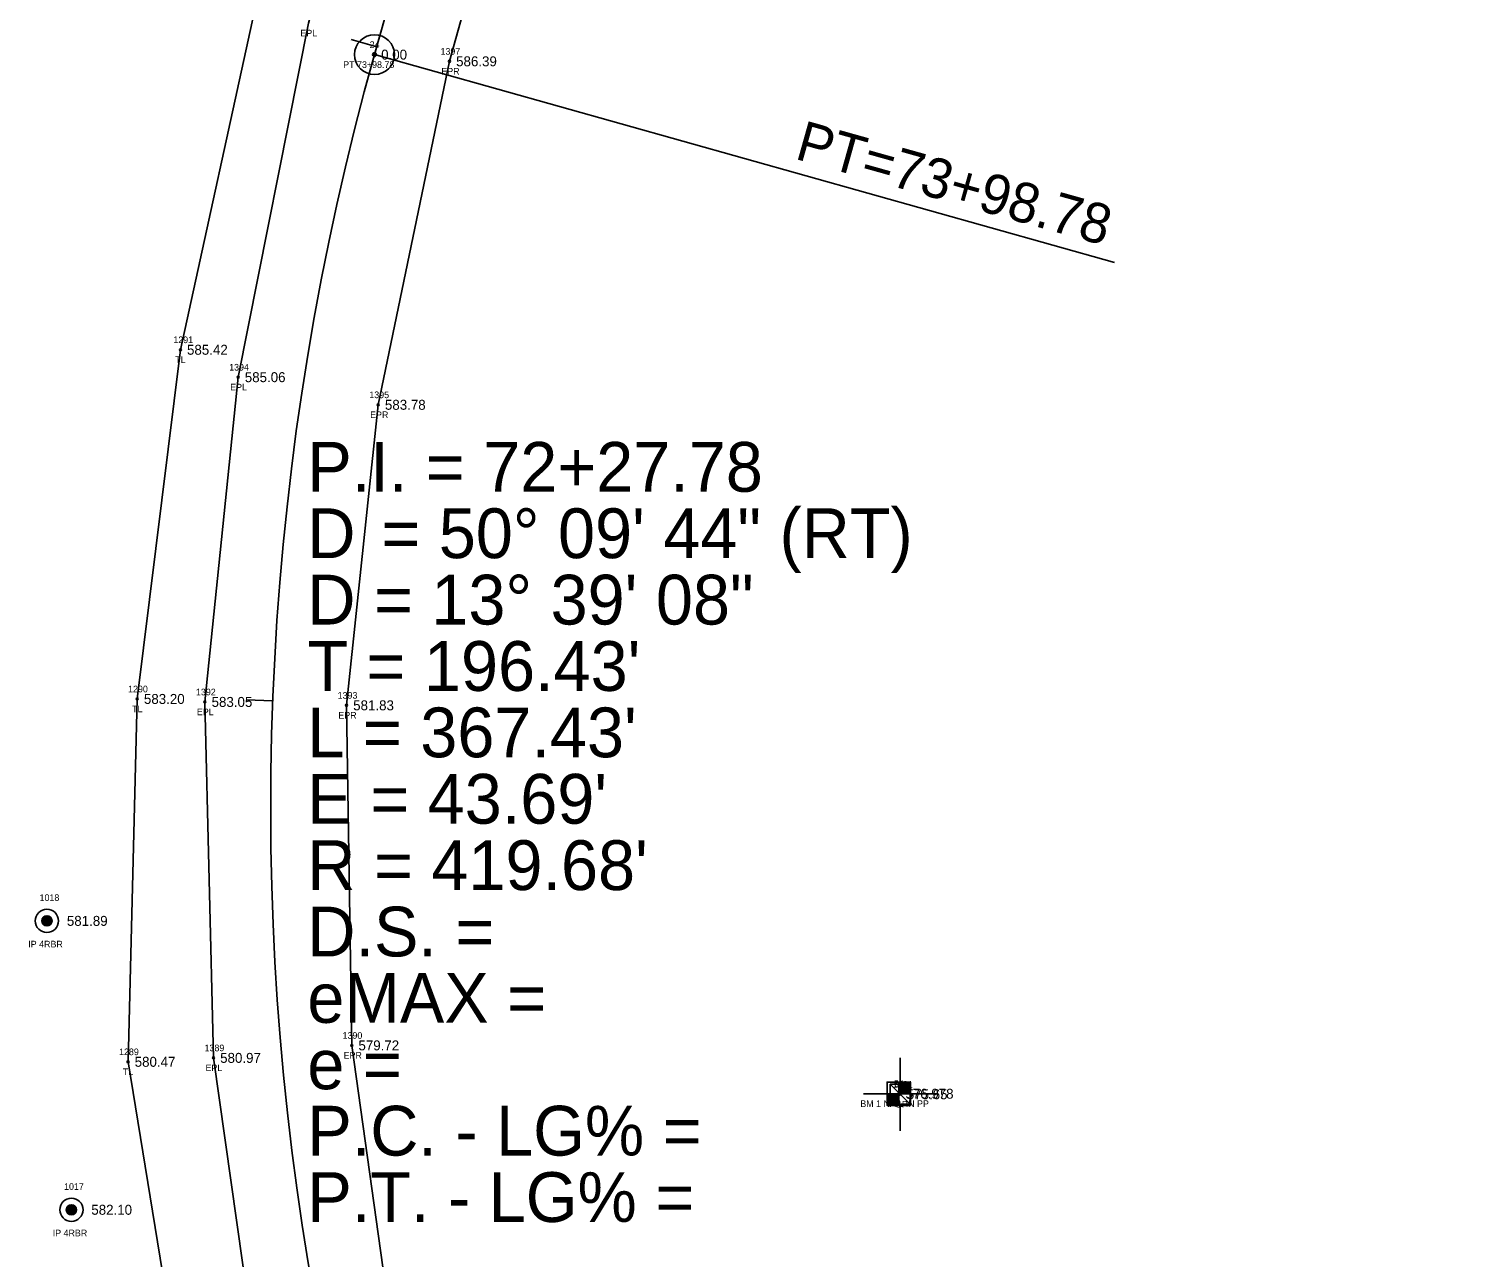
# Model space of a CAD drawing. Extents: x 1694813 to 1696862, y 1086485 to 1091027.
# Drawn here: x 1695680.1 to 1695899, y 1089351.6 to 1089536.7 of the extents above; entities that cross this region are included whole.
import ezdxf

# ---------------------------------------------------------------- set-up
doc = ezdxf.new("R2010")
doc.units = 0
for name, color, linetype in [('RD_EX_DV_Prop_txCode', 7, 'Continuous'), ('RD_EX_DV_PropPin', 7, 'Continuous'), ('RD_EX_Road', 7, 'Continuous'), ('RD_EX_Road_txCode', 7, 'Continuous'), ('RD_EX_TX_DV_Prop_ELEV', 7, 'Continuous'), ('RD_EX_TX_Road_ELEV', 7, 'Continuous'), ('RD_EX_TX_UT_ELEV', 7, 'Continuous'), ('RD_EX_TX_VEG_ELEV', 7, 'Continuous'), ('RD_EX_UT', 7, 'Continuous'), ('RD_EX_UT_txCode', 7, 'Continuous'), ('RD_EX_VEG', 7, 'Continuous'), ('RD_EX_VEG_txCode', 7, 'Continuous'), ('RD_HC_Cl', 7, 'Continuous'), ('RD_HC_Data', 7, 'Continuous'), ('RD_HC_Data_Tic', 7, 'Continuous'), ('RD_HC_Survey', 7, 'Continuous'), ('RD_HC_Survey_ELEV', 7, 'Continuous'), ('RD_HC_Survey_txCode', 7, 'Continuous'), ('RD_HC_txCode', 7, 'Continuous'), ('RD_SMD_Locator', 7, 'Continuous')]:
    doc.layers.add(name, color=color, linetype=linetype)

msp = doc.modelspace()

# ---------------------------------------------------------------- linework, layer by layer
at = {"layer": 'RD_EX_DV_PropPin'}
for p, q in [((1695682.05, 1089402.17), (1695682.05, 1089402.56)), ((1695682.09, 1089402.07), (1695682.09, 1089402.66)), ((1695682.12, 1089401.99), (1695682.12, 1089402.73)), ((1695682.16, 1089401.94), (1695682.16, 1089402.79)), ((1695682.19, 1089401.89), (1695682.19, 1089402.84)), ((1695682.23, 1089401.85), (1695682.23, 1089402.88)), ((1695682.26, 1089401.81), (1695682.26, 1089402.91)), ((1695682.3, 1089401.78), (1695682.3, 1089402.95)), ((1695682.33, 1089401.75), (1695682.33, 1089402.97)), ((1695682.37, 1089401.73), (1695682.37, 1089403)), ((1695682.4, 1089401.71), (1695682.4, 1089403.02)), ((1695682.44, 1089401.69), (1695682.44, 1089403.04)), ((1695682.47, 1089401.67), (1695682.47, 1089403.06)), ((1695682.51, 1089401.66), (1695682.51, 1089403.07)), ((1695682.54, 1089401.64), (1695682.54, 1089403.08)), ((1695682.58, 1089401.63), (1695682.58, 1089403.1)), ((1695682.61, 1089401.62), (1695682.61, 1089403.1)), ((1695682.65, 1089401.62), (1695682.65, 1089403.11)), ((1695682.68, 1089401.61), (1695682.68, 1089403.12)), ((1695682.72, 1089401.61), (1695682.72, 1089403.12)), ((1695682.75, 1089401.6), (1695682.75, 1089403.12)), ((1695682.79, 1089401.6), (1695682.79, 1089403.12)), ((1695682.82, 1089401.6), (1695682.82, 1089403.12)), ((1695682.86, 1089401.61), (1695682.86, 1089403.12)), ((1695682.89, 1089401.61), (1695682.89, 1089403.12)), ((1695682.93, 1089401.62), (1695682.93, 1089403.11)), ((1695682.96, 1089401.62), (1695682.96, 1089403.1)), ((1695683, 1089401.63), (1695683, 1089403.1)), ((1695683.03, 1089401.64), (1695683.03, 1089403.08)), ((1695683.07, 1089401.66), (1695683.07, 1089403.07)), ((1695683.1, 1089401.67), (1695683.1, 1089403.06)), ((1695683.14, 1089401.69), (1695683.14, 1089403.04)), ((1695683.17, 1089401.71), (1695683.17, 1089403.02)), ((1695683.21, 1089401.73), (1695683.21, 1089403)), ((1695683.24, 1089401.75), (1695683.24, 1089402.97)), ((1695683.28, 1089401.78), (1695683.28, 1089402.95)), ((1695683.31, 1089401.81), (1695683.31, 1089402.91)), ((1695683.35, 1089401.85), (1695683.35, 1089402.88)), ((1695683.38, 1089401.89), (1695683.38, 1089402.84)), ((1695683.42, 1089401.94), (1695683.42, 1089402.79)), ((1695683.45, 1089401.99), (1695683.45, 1089402.73)), ((1695683.49, 1089402.07), (1695683.49, 1089402.66)), ((1695683.52, 1089402.17), (1695683.52, 1089402.56)), ((1695685.73, 1089358.64), (1695685.73, 1089359.03)), ((1695685.77, 1089358.54), (1695685.77, 1089359.14)), ((1695685.8, 1089358.47), (1695685.8, 1089359.21)), ((1695685.84, 1089358.41), (1695685.84, 1089359.26)), ((1695685.87, 1089358.36), (1695685.87, 1089359.31)), ((1695685.91, 1089358.32), (1695685.91, 1089359.35)), ((1695685.94, 1089358.29), (1695685.94, 1089359.39)), ((1695685.98, 1089358.26), (1695685.98, 1089359.42)), ((1695686.01, 1089358.23), (1695686.01, 1089359.45)), ((1695686.05, 1089358.2), (1695686.05, 1089359.47)), ((1695686.08, 1089358.18), (1695686.08, 1089359.49)), ((1695686.12, 1089358.16), (1695686.12, 1089359.51)), ((1695686.15, 1089358.15), (1695686.15, 1089359.53)), ((1695686.19, 1089358.13), (1695686.19, 1089359.55)), ((1695686.22, 1089358.12), (1695686.22, 1089359.56)), ((1695686.26, 1089358.11), (1695686.26, 1089359.57)), ((1695686.29, 1089358.1), (1695686.29, 1089359.58)), ((1695686.33, 1089358.09), (1695686.33, 1089359.59)), ((1695686.36, 1089358.08), (1695686.36, 1089359.59)), ((1695686.4, 1089358.08), (1695686.4, 1089359.6)), ((1695686.43, 1089358.08), (1695686.43, 1089359.6)), ((1695686.47, 1089358.08), (1695686.47, 1089359.6)), ((1695686.5, 1089358.08), (1695686.5, 1089359.6)), ((1695686.54, 1089358.08), (1695686.54, 1089359.6)), ((1695686.57, 1089358.08), (1695686.57, 1089359.59)), ((1695686.61, 1089358.09), (1695686.61, 1089359.59)), ((1695686.64, 1089358.1), (1695686.64, 1089359.58)), ((1695686.68, 1089358.11), (1695686.68, 1089359.57)), ((1695686.71, 1089358.12), (1695686.71, 1089359.56)), ((1695686.75, 1089358.13), (1695686.75, 1089359.55)), ((1695686.78, 1089358.15), (1695686.78, 1089359.53)), ((1695686.82, 1089358.16), (1695686.82, 1089359.51)), ((1695686.85, 1089358.18), (1695686.85, 1089359.49)), ((1695686.89, 1089358.2), (1695686.89, 1089359.47)), ((1695686.92, 1089358.23), (1695686.92, 1089359.45)), ((1695686.96, 1089358.26), (1695686.96, 1089359.42)), ((1695686.99, 1089358.29), (1695686.99, 1089359.39)), ((1695687.03, 1089358.32), (1695687.03, 1089359.35)), ((1695687.06, 1089358.36), (1695687.06, 1089359.31)), ((1695687.1, 1089358.41), (1695687.1, 1089359.26)), ((1695687.13, 1089358.47), (1695687.13, 1089359.21)), ((1695687.17, 1089358.54), (1695687.17, 1089359.14)), ((1695687.2, 1089358.64), (1695687.2, 1089359.03))]:
    msp.add_line(p, q, dxfattribs=at)
for centre, radius in [((1695682.79, 1089402.36), 1.75), ((1695682.79, 1089402.36), 0.761), ((1695686.47, 1089358.84), 1.75), ((1695686.47, 1089358.84), 0.761)]:
    msp.add_circle(centre, radius, dxfattribs=at)
at = {"layer": 'RD_EX_Road'}
for points in [[(1695813.78, 1089148.1), (1695805.56, 1089142.08), (1695776.44, 1089183.94), (1695749.27, 1089231.88), (1695730.49, 1089275.72), (1695714.87, 1089332.12), (1695707.87, 1089381.72), (1695706.58, 1089435.34), (1695711.58, 1089484.26), (1695722.15, 1089537.59), (1695749.04, 1089634.88), (1695776.11, 1089730.43), (1695788.13, 1089777.42), (1695798.89, 1089826.76), (1695807.1, 1089870.03), (1695814.71, 1089923.3), (1695820.51, 1089978.16), (1695824.04, 1090019.79), (1695832.76, 1090119.06), (1695841.25, 1090216.76), (1695850.36, 1090314.41), (1695859.24, 1090411.82), (1695868.09, 1090511.63), (1695876.75, 1090608.38)], [(1695735.35, 1089335.84), (1695728.69, 1089383.6), (1695727.9, 1089434.83), (1695732.68, 1089480.1), (1695743.4, 1089531.84), (1695770.35, 1089628.36), (1695797.63, 1089725.22), (1695809.49, 1089772.37), (1695818.34, 1089811.57), (1695820.65, 1089823.41), (1695822.99, 1089835.26), (1695829.18, 1089869.37), (1695836.32, 1089920.97), (1695842.44, 1089975.46), (1695846.49, 1090018.55), (1695849.32, 1090055.39), (1695850.91, 1090072.92), (1695855.09, 1090117.49), (1695863.53, 1090214.93), (1695872.56, 1090312.44), (1695881.69, 1090410.78), (1695890.45, 1090509.3), (1695899.01, 1090605.4)]]:
    msp.add_lwpolyline(points, dxfattribs=at)
at = {"layer": 'RD_EX_UT'}
for p, q in [((1695811.26, 1089377.74), (1695811.26, 1089381.74)), ((1695809.73, 1089376.28), (1695805.73, 1089376.28)), ((1695812.76, 1089377.74), (1695809.76, 1089374.74)), ((1695809.76, 1089377.74), (1695812.76, 1089374.74)), ((1695812.76, 1089377.74), (1695809.76, 1089377.74)), ((1695809.76, 1089377.74), (1695809.76, 1089374.74)), ((1695812.76, 1089374.74), (1695812.76, 1089377.74)), ((1695812.77, 1089376.3), (1695816.79, 1089376.3)), ((1695809.76, 1089374.74), (1695812.76, 1089374.74)), ((1695811.26, 1089374.74), (1695811.26, 1089370.74))]:
    msp.add_line(p, q, dxfattribs=at)
at = {"layer": 'RD_EX_VEG'}
msp.add_lwpolyline([(1695703.52, 1089329.03), (1695695, 1089381.13), (1695696.39, 1089435.79), (1695702.88, 1089488.39), (1695714.38, 1089541.02), (1695736.44, 1089639.8), (1695727.2, 1089683.67), (1695743.97, 1089747.86), (1695756.74, 1089783.05), (1695766.78, 1089823.73), (1695779.53, 1089881.29), (1695754.55, 1089939.82)], dxfattribs=at)
at = {"layer": 'RD_HC_Cl'}
msp.add_line((1695732.11, 1089532.85), (1695785.9, 1089724.36), dxfattribs=at)
msp.add_arc((1696136.16, 1089419.37), 419.68, 164.3126, 214.4747, dxfattribs=at)
at = {"layer": 'RD_HC_Data'}
msp.add_line((1695732.11, 1089532.85), (1695843.51, 1089501.56), dxfattribs=at)
for radius in [3, 0.282]:
    msp.add_circle((1695732.11, 1089532.85), radius, dxfattribs=at)
at = {"layer": 'RD_HC_Data_Tic'}
for p, q in [((1695732.44, 1089534.02), (1695728.59, 1089535.11)), ((1695716.79, 1089435.5), (1695712.79, 1089435.65))]:
    msp.add_line(p, q, dxfattribs=at)
at = {"layer": 'RD_HC_Survey'}
for p, q in [((1695811.05, 1089378.07), (1695811.05, 1089374.57)), ((1695811.06, 1089378.07), (1695811.06, 1089376.32)), ((1695811.09, 1089378.07), (1695811.09, 1089376.32)), ((1695811.11, 1089378.07), (1695811.11, 1089376.32)), ((1695811.14, 1089378.07), (1695811.14, 1089376.32)), ((1695811.16, 1089378.07), (1695811.16, 1089376.32)), ((1695811.19, 1089378.07), (1695811.19, 1089376.32)), ((1695811.21, 1089378.07), (1695811.21, 1089376.32)), ((1695811.24, 1089378.07), (1695811.24, 1089376.32)), ((1695811.26, 1089378.07), (1695811.26, 1089376.32)), ((1695811.29, 1089378.07), (1695811.29, 1089376.32)), ((1695811.31, 1089378.07), (1695811.31, 1089376.32)), ((1695811.34, 1089378.07), (1695811.34, 1089376.32)), ((1695811.36, 1089378.07), (1695811.36, 1089376.32)), ((1695811.38, 1089378.07), (1695811.38, 1089376.32)), ((1695811.41, 1089378.07), (1695811.41, 1089376.32)), ((1695811.43, 1089378.07), (1695811.43, 1089376.32)), ((1695811.46, 1089378.07), (1695811.46, 1089376.32)), ((1695811.48, 1089378.07), (1695811.48, 1089376.32)), ((1695811.51, 1089378.07), (1695811.51, 1089376.32)), ((1695811.53, 1089378.07), (1695811.53, 1089376.32)), ((1695811.56, 1089378.07), (1695811.56, 1089376.32)), ((1695811.58, 1089378.07), (1695811.58, 1089376.32)), ((1695811.61, 1089378.07), (1695811.61, 1089376.32)), ((1695811.63, 1089378.07), (1695811.63, 1089376.32)), ((1695811.66, 1089378.07), (1695811.66, 1089376.32)), ((1695811.68, 1089378.07), (1695811.68, 1089376.32)), ((1695811.71, 1089378.07), (1695811.71, 1089376.32)), ((1695811.73, 1089378.07), (1695811.73, 1089376.32)), ((1695811.76, 1089378.07), (1695811.76, 1089376.32)), ((1695811.78, 1089378.07), (1695811.78, 1089376.32)), ((1695811.81, 1089378.07), (1695811.81, 1089376.32)), ((1695811.83, 1089378.07), (1695811.83, 1089376.32)), ((1695811.86, 1089378.07), (1695811.86, 1089376.32)), ((1695811.88, 1089378.07), (1695811.88, 1089376.32)), ((1695811.9, 1089378.07), (1695811.9, 1089376.32)), ((1695811.93, 1089378.07), (1695811.93, 1089376.32)), ((1695811.95, 1089378.07), (1695811.95, 1089376.32)), ((1695811.98, 1089378.07), (1695811.98, 1089376.32)), ((1695812, 1089378.07), (1695812, 1089376.32)), ((1695812.03, 1089378.07), (1695812.03, 1089376.32)), ((1695812.05, 1089378.07), (1695812.05, 1089376.32)), ((1695812.08, 1089378.07), (1695812.08, 1089376.32)), ((1695812.1, 1089378.07), (1695812.1, 1089376.32)), ((1695812.13, 1089378.07), (1695812.13, 1089376.32)), ((1695812.15, 1089378.07), (1695812.15, 1089376.32)), ((1695812.18, 1089378.07), (1695812.18, 1089376.32)), ((1695812.2, 1089378.07), (1695812.2, 1089376.32)), ((1695812.23, 1089378.07), (1695812.23, 1089376.32)), ((1695812.25, 1089378.07), (1695812.25, 1089376.32)), ((1695812.28, 1089378.07), (1695812.28, 1089376.32)), ((1695812.3, 1089378.07), (1695812.3, 1089376.32)), ((1695812.33, 1089378.07), (1695812.33, 1089376.32)), ((1695812.35, 1089378.07), (1695812.35, 1089376.32)), ((1695812.37, 1089378.07), (1695812.37, 1089376.32)), ((1695812.4, 1089378.07), (1695812.4, 1089376.32)), ((1695812.42, 1089378.07), (1695812.42, 1089376.32)), ((1695812.45, 1089378.07), (1695812.45, 1089376.32)), ((1695812.47, 1089378.07), (1695812.47, 1089376.32)), ((1695812.5, 1089378.07), (1695812.5, 1089376.32)), ((1695812.52, 1089378.07), (1695812.52, 1089376.32)), ((1695812.55, 1089378.07), (1695812.55, 1089376.32)), ((1695812.57, 1089378.07), (1695812.57, 1089376.32)), ((1695812.6, 1089378.07), (1695812.6, 1089376.32)), ((1695812.62, 1089378.07), (1695812.62, 1089376.32)), ((1695812.65, 1089378.07), (1695812.65, 1089376.32)), ((1695812.67, 1089378.07), (1695812.67, 1089376.32)), ((1695812.7, 1089378.07), (1695812.7, 1089376.32)), ((1695812.72, 1089378.07), (1695812.72, 1089376.32)), ((1695812.75, 1089378.07), (1695812.75, 1089376.32)), ((1695812.77, 1089378.07), (1695812.77, 1089376.32)), ((1695812.8, 1089376.32), (1695809.3, 1089376.32)), ((1695809.3, 1089376.32), (1695809.3, 1089374.57)), ((1695809.32, 1089376.32), (1695809.32, 1089374.57)), ((1695809.35, 1089376.32), (1695809.35, 1089374.57)), ((1695809.37, 1089376.32), (1695809.37, 1089374.57)), ((1695809.39, 1089376.32), (1695809.39, 1089374.57)), ((1695809.42, 1089376.32), (1695809.42, 1089374.57)), ((1695809.44, 1089376.32), (1695809.44, 1089374.57)), ((1695809.47, 1089376.32), (1695809.47, 1089374.57)), ((1695809.49, 1089376.32), (1695809.49, 1089374.57)), ((1695809.52, 1089376.32), (1695809.52, 1089374.57)), ((1695809.54, 1089376.32), (1695809.54, 1089374.57)), ((1695809.57, 1089376.32), (1695809.57, 1089374.57)), ((1695809.59, 1089376.32), (1695809.59, 1089374.57)), ((1695809.62, 1089376.32), (1695809.62, 1089374.57)), ((1695809.64, 1089376.32), (1695809.64, 1089374.57)), ((1695809.67, 1089376.32), (1695809.67, 1089374.57)), ((1695809.69, 1089376.32), (1695809.69, 1089374.57)), ((1695809.72, 1089376.32), (1695809.72, 1089374.57)), ((1695809.74, 1089376.32), (1695809.74, 1089374.57)), ((1695809.77, 1089376.32), (1695809.77, 1089374.57)), ((1695809.79, 1089376.32), (1695809.79, 1089374.57)), ((1695809.82, 1089376.32), (1695809.82, 1089374.57)), ((1695809.84, 1089376.32), (1695809.84, 1089374.57)), ((1695809.86, 1089376.32), (1695809.86, 1089374.57)), ((1695809.89, 1089376.32), (1695809.89, 1089374.57)), ((1695809.91, 1089376.32), (1695809.91, 1089374.57)), ((1695809.94, 1089376.32), (1695809.94, 1089374.57)), ((1695809.96, 1089376.32), (1695809.96, 1089374.57)), ((1695809.99, 1089376.32), (1695809.99, 1089374.57)), ((1695810.01, 1089376.32), (1695810.01, 1089374.57)), ((1695810.04, 1089376.32), (1695810.04, 1089374.57)), ((1695810.06, 1089376.32), (1695810.06, 1089374.57)), ((1695810.09, 1089376.32), (1695810.09, 1089374.57)), ((1695810.11, 1089376.32), (1695810.11, 1089374.57)), ((1695810.14, 1089376.32), (1695810.14, 1089374.57)), ((1695810.16, 1089376.32), (1695810.16, 1089374.57)), ((1695810.19, 1089376.32), (1695810.19, 1089374.57)), ((1695810.21, 1089376.32), (1695810.21, 1089374.57)), ((1695810.24, 1089376.32), (1695810.24, 1089374.57)), ((1695810.26, 1089376.32), (1695810.26, 1089374.57)), ((1695810.29, 1089376.32), (1695810.29, 1089374.57)), ((1695810.31, 1089376.32), (1695810.31, 1089374.57)), ((1695810.34, 1089376.32), (1695810.34, 1089374.57)), ((1695810.36, 1089376.32), (1695810.36, 1089374.57)), ((1695810.38, 1089376.32), (1695810.38, 1089374.57)), ((1695810.41, 1089376.32), (1695810.41, 1089374.57)), ((1695810.43, 1089376.32), (1695810.43, 1089374.57)), ((1695810.46, 1089376.32), (1695810.46, 1089374.57)), ((1695810.48, 1089376.32), (1695810.48, 1089374.57)), ((1695810.51, 1089376.32), (1695810.51, 1089374.57)), ((1695810.53, 1089376.32), (1695810.53, 1089374.57)), ((1695810.56, 1089376.32), (1695810.56, 1089374.57)), ((1695810.58, 1089376.32), (1695810.58, 1089374.57)), ((1695810.61, 1089376.32), (1695810.61, 1089374.57)), ((1695810.63, 1089376.32), (1695810.63, 1089374.57)), ((1695810.66, 1089376.32), (1695810.66, 1089374.57)), ((1695810.68, 1089376.32), (1695810.68, 1089374.57)), ((1695810.71, 1089376.32), (1695810.71, 1089374.57)), ((1695810.73, 1089376.32), (1695810.73, 1089374.57)), ((1695810.76, 1089376.32), (1695810.76, 1089374.57)), ((1695810.78, 1089376.32), (1695810.78, 1089374.57)), ((1695810.81, 1089376.32), (1695810.81, 1089374.57)), ((1695810.83, 1089376.32), (1695810.83, 1089374.57)), ((1695810.85, 1089376.32), (1695810.85, 1089374.57)), ((1695810.88, 1089376.32), (1695810.88, 1089374.57)), ((1695810.9, 1089376.32), (1695810.9, 1089374.57)), ((1695810.93, 1089376.32), (1695810.93, 1089374.57)), ((1695810.95, 1089376.32), (1695810.95, 1089374.57)), ((1695810.98, 1089376.32), (1695810.98, 1089374.57)), ((1695811, 1089376.32), (1695811, 1089374.57)), ((1695811.03, 1089376.32), (1695811.03, 1089374.57))]:
    msp.add_line(p, q, dxfattribs=at)
msp.add_lwpolyline([(1695812.8, 1089378.07), (1695809.3, 1089378.07), (1695809.3, 1089374.57), (1695812.8, 1089374.57)], close=True, dxfattribs=at)
at = {"layer": 'RD_SMD_Locator'}
for centre in [(1695732.11, 1089532.85), (1695743.4, 1089531.84), (1695702.88, 1089488.39), (1695711.58, 1089484.26), (1695732.68, 1089480.1), (1695696.39, 1089435.79), (1695706.58, 1089435.34), (1695727.9, 1089434.83), (1695682.79, 1089402.36), (1695728.69, 1089383.6), (1695695, 1089381.13), (1695707.87, 1089381.72), (1695811.05, 1089376.32), (1695811.26, 1089376.24), (1695686.47, 1089358.84)]:
    msp.add_circle(centre, 0.15, dxfattribs=at)

# ---------------------------------------------------------------- texts
at = {"layer": 'RD_EX_DV_Prop_txCode'}
for s, p in [('1018', (1695681.68, 1089405.36)), ('IP 4RBR', (1695679.98, 1089398.36)), ('1017', (1695685.37, 1089361.84)), ('IP 4RBR', (1695683.66, 1089354.84))]:
    msp.add_text(s, height=1, dxfattribs=at).set_placement(p)
at = {"layer": 'RD_EX_Road_txCode'}
for s, p in [('EPL', (1695720.95, 1089535.59)), ('1397', (1695742.05, 1089532.84)), ('EPR', (1695742.17, 1089529.84)), ('1394', (1695710.23, 1089485.26)), ('EPL', (1695710.38, 1089482.26)), ('1395', (1695731.33, 1089481.1)), ('EPR', (1695731.45, 1089478.1)), ('1392', (1695705.23, 1089436.34)), ('1393', (1695726.56, 1089435.83)), ('EPL', (1695705.37, 1089433.34)), ('EPR', (1695726.67, 1089432.83)), ('1390', (1695727.3, 1089384.6)), ('1389', (1695706.52, 1089382.72)), ('EPR', (1695727.46, 1089381.6)), ('EPL', (1695706.66, 1089379.72))]:
    msp.add_text(s, height=1, dxfattribs=at).set_placement(p)
at = {"layer": 'RD_EX_TX_DV_Prop_ELEV'}
for s, p in [('581.89', (1695685.79, 1089401.61)), ('582.10', (1695689.47, 1089358.09))]:
    msp.add_text(s, height=1.5, dxfattribs=at).set_placement(p)
at = {"layer": 'RD_EX_TX_Road_ELEV'}
for s, p in [('586.39', (1695744.4, 1089531.09)), ('585.06', (1695712.58, 1089483.51)), ('583.78', (1695733.68, 1089479.35)), ('583.05', (1695707.58, 1089434.59)), ('581.83', (1695728.9, 1089434.08)), ('580.97', (1695708.87, 1089380.97)), ('579.72', (1695729.69, 1089382.85))]:
    msp.add_text(s, height=1.5, dxfattribs=at).set_placement(p)
at = {"layer": 'RD_EX_TX_UT_ELEV'}
msp.add_text('575.65', height=1.5, dxfattribs=at).set_placement((1695812.26, 1089375.49))
at = {"layer": 'RD_EX_TX_VEG_ELEV'}
for s, p in [('585.42', (1695703.88, 1089487.64)), ('583.20', (1695697.39, 1089435.04)), ('580.47', (1695696, 1089380.38))]:
    msp.add_text(s, height=1.5, dxfattribs=at).set_placement(p)
at = {"layer": 'RD_EX_UT_txCode'}
for s, p in [('1391', (1695810.19, 1089377.24)), ('GP', (1695810.48, 1089374.24))]:
    msp.add_text(s, height=1, dxfattribs=at).set_placement(p)
at = {"layer": 'RD_EX_VEG_txCode'}
for s, p in [('1291', (1695701.82, 1089489.39)), ('TL', (1695702.11, 1089486.39)), ('1290', (1695695.01, 1089436.79)), ('TL', (1695695.62, 1089433.79)), ('1289', (1695693.65, 1089382.13)), ('TL', (1695694.23, 1089379.13))]:
    msp.add_text(s, height=1, dxfattribs=at).set_placement(p)
at = {"layer": 'RD_HC_Data'}
msp.add_text('PT=73+98.78', height=6, rotation=344.3126, dxfattribs=at).set_placement((1695795.23, 1089517.2))
for s, p in [('P.I. = 72+27.78', (1695722, 1089467)), ('D', (1695722, 1089457)), ('    = 50%%d 09\' 44" (RT)', (1695722, 1089457)), ('D = 13%%d 39\' 08"', (1695722, 1089447)), ("T = 196.43'", (1695722, 1089437)), ("L = 367.43'", (1695722, 1089427)), ("E = 43.69'", (1695722, 1089417)), ("R = 419.68'", (1695722, 1089407)), ('D.S. = ', (1695722, 1089397)), ('eMAX = ', (1695722, 1089387)), ('e = ', (1695722, 1089377)), ('P.C. - LG% = ', (1695722, 1089367)), ('P.T. - LG% = ', (1695722, 1089357))]:
    msp.add_text(s, height=7.5, dxfattribs=at).set_placement(p)
at = {"layer": 'RD_HC_Survey_ELEV'}
for s, p in [('0.00', (1695733.11, 1089532.1)), ('576.978', (1695812.05, 1089375.57))]:
    msp.add_text(s, height=1.5, dxfattribs=at).set_placement(p)
at = {"layer": 'RD_HC_Survey_txCode'}
for s, p in [('54', (1695810.31, 1089377.32)), ('BM 1 NAIL IN PP', (1695805.26, 1089374.32))]:
    msp.add_text(s, height=1, dxfattribs=at).set_placement(p)
at = {"layer": 'RD_HC_txCode'}
for s, p in [('24', (1695731.38, 1089533.85)), ('PT 73+98.78', (1695727.4, 1089530.85))]:
    msp.add_text(s, height=1, dxfattribs=at).set_placement(p)

doc.saveas('drawing.dxf')
